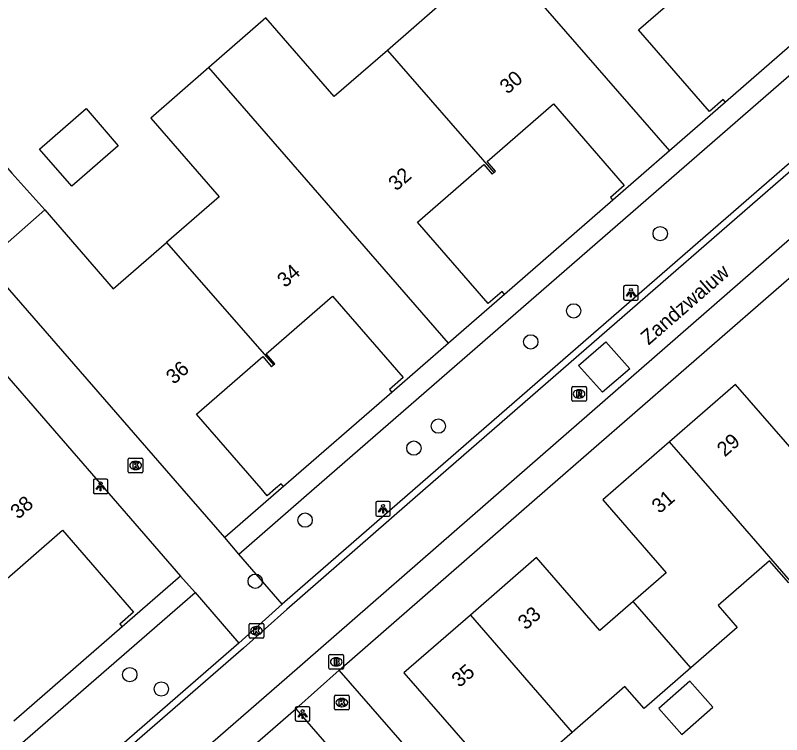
# Model space of a CAD drawing. Extents: x 155888 to 156864, y 383882 to 384671.
# Drawn here: x 156227.5 to 156279.9, y 384233.2 to 384282.3 of the extents above; entities that cross this region are included whole.
import ezdxf

# ---------------------------------------------------------------- set-up
doc = ezdxf.new("R2010")
doc.units = 0
for name, color, linetype in [('IMGEO_Boom', 7, 'Continuous'), ('IMGEO_Brandkraan', 7, 'Continuous'), ('IMGEO_Kolk', 7, 'Continuous'), ('IMGEO_Lichtpunt', 7, 'Continuous'), ('IMGEO_Openbare_ruimte_label', 7, 'Continuous'), ('IMGEO_Pand', 7, 'Continuous'), ('IMGEO_Pand_nummerreeks', 7, 'Continuous'), ('IMGEO_Rijbaan_lokaal_gesloten', 7, 'Continuous'), ('IMGEO_Rijbaan_lokaal_open', 7, 'Continuous'), ('IMGEO_Rioolput', 7, 'Continuous'), ('IMGEO_Voetpad_open', 7, 'Continuous')]:
    doc.layers.add(name, color=color, linetype=linetype)

msp = doc.modelspace()

# ---------------------------------------------------------------- linework, layer by layer
at = {"layer": 'IMGEO_Boom'}
for centre in [(156271.565, 384267.4), (156265.659, 384262.13), (156262.726, 384260.015), (156256.417, 384254.264), (156254.745, 384252.761), (156247.318, 384247.848), (156243.914, 384243.68), (156235.344, 384237.306), (156237.497, 384236.332)]:
    msp.add_circle(centre, 0.489, dxfattribs=at)
at = {"layer": 'IMGEO_Brandkraan'}
for p, q in [((156248.947, 384237.751), (156248.947, 384238.603)), ((156249.022, 384238.677), (156249.874, 384238.677)), ((156249.435, 384238.457), (156249.46, 384238.457)), ((156249.948, 384238.603), (156249.948, 384237.751)), ((156249.874, 384237.677), (156249.022, 384237.677)), ((156249.458, 384237.897), (156249.433, 384237.897))]:
    msp.add_line(p, q, dxfattribs=at)
for points in [[(156248.947, 384237.751), (156248.947, 384238.603)], [(156249.022, 384238.677), (156249.874, 384238.677)], [(156249.295, 384238.377), (156249.295, 384237.977), (156249.508, 384237.977)], [(156249.526, 384238.377), (156249.295, 384238.377)], [(156249.474, 384238.296), (156249.42, 384238.296), (156249.42, 384238.22)], [(156249.42, 384238.22), (156249.473, 384238.22)], [(156249.948, 384238.603), (156249.948, 384237.751)], [(156249.874, 384237.677), (156249.022, 384237.677)], [(156249.482, 384238.144), (156249.42, 384238.144), (156249.42, 384238.063)], [(156249.42, 384238.063), (156249.482, 384238.063)]]:
    msp.add_lwpolyline(points, dxfattribs=at)
for centre, radius, start, end in [((156249.024, 384238.601), 0.0765, 91.552, 178.448), ((156249.024, 384238.601), 0.0765, 91.552, 178.448), ((156249.475, 384238.258), 0.0379, 267.8285, 90.9355), ((156249.53, 384238.232), 0.145, 59.4692, 91.5367), ((156249.555, 384238.279), 0.0922, 285.5137, 58.1501), ((156249.56, 384238.087), 0.105, 301.3115, 78.989), ((156249.872, 384238.601), 0.0765, 1.552, 88.448), ((156249.872, 384238.601), 0.0765, 1.552, 88.448), ((156249.024, 384237.753), 0.0765, 181.552, 268.448), ((156249.024, 384237.753), 0.0765, 181.552, 268.448), ((156249.483, 384238.103), 0.0404, 269.8759, 90.5077), ((156249.514, 384238.228), 0.251, 268.6676, 293.5347), ((156249.872, 384237.753), 0.0765, 271.552, 358.448), ((156249.872, 384237.753), 0.0765, 271.552, 358.448)]:
    msp.add_arc(centre, radius, start, end, dxfattribs=at)
for centre, major_axis, ratio, start_param, end_param in [((156249.434, 384238.177), (-0.387, 0.002), 0.722429, 4.712389, 7.853982), ((156249.459, 384238.177), (-0.39, 0.002), 0.717154, 1.570796, 4.712389)]:
    msp.add_ellipse(centre, major_axis=major_axis, ratio=ratio, start_param=start_param, end_param=end_param, dxfattribs=at)
at = {"layer": 'IMGEO_Kolk'}
for p, q in [((156235.246, 384251.155), (156235.246, 384252.007)), ((156235.321, 384252.081), (156236.173, 384252.081)), ((156235.734, 384251.861), (156235.759, 384251.861)), ((156236.247, 384252.007), (156236.247, 384251.155)), ((156235.757, 384251.301), (156235.732, 384251.301)), ((156236.173, 384251.081), (156235.321, 384251.081)), ((156243.565, 384240.802), (156244.417, 384240.802)), ((156243.49, 384239.876), (156243.49, 384240.728)), ((156243.978, 384240.582), (156244.003, 384240.582)), ((156244.491, 384240.728), (156244.491, 384239.876)), ((156244.417, 384239.802), (156243.565, 384239.802)), ((156244.001, 384240.022), (156243.976, 384240.022)), ((156249.325, 384234.974), (156249.325, 384235.826)), ((156249.4, 384235.9), (156250.252, 384235.9)), ((156249.813, 384235.68), (156249.838, 384235.68)), ((156250.326, 384235.826), (156250.326, 384234.974)), ((156249.836, 384235.12), (156249.811, 384235.12)), ((156250.252, 384234.9), (156249.4, 384234.9))]:
    msp.add_line(p, q, dxfattribs=at)
for points in [[(156235.246, 384251.155), (156235.246, 384252.007)], [(156235.321, 384252.081), (156236.173, 384252.081)], [(156235.567, 384251.781), (156235.69, 384251.781), (156235.69, 384251.63), (156235.82, 384251.781), (156235.984, 384251.781), (156235.838, 384251.63), (156235.991, 384251.381), (156235.839, 384251.381), (156235.754, 384251.545), (156235.69, 384251.478), (156235.69, 384251.381), (156235.567, 384251.381), (156235.567, 384251.781)], [(156236.247, 384252.007), (156236.247, 384251.155)], [(156236.173, 384251.081), (156235.321, 384251.081)], [(156243.565, 384240.802), (156244.417, 384240.802)], [(156243.49, 384239.876), (156243.49, 384240.728)], [(156243.811, 384240.502), (156243.934, 384240.502), (156243.934, 384240.351), (156244.064, 384240.502), (156244.228, 384240.502), (156244.082, 384240.351), (156244.235, 384240.102), (156244.083, 384240.102), (156243.998, 384240.266), (156243.934, 384240.199), (156243.934, 384240.102), (156243.811, 384240.102), (156243.811, 384240.502)], [(156244.491, 384240.728), (156244.491, 384239.876)], [(156244.417, 384239.802), (156243.565, 384239.802)], [(156249.325, 384234.974), (156249.325, 384235.826)], [(156249.4, 384235.9), (156250.252, 384235.9)], [(156249.646, 384235.6), (156249.769, 384235.6), (156249.769, 384235.449), (156249.899, 384235.6), (156250.063, 384235.6), (156249.917, 384235.449), (156250.07, 384235.2), (156249.918, 384235.2), (156249.833, 384235.364), (156249.769, 384235.297), (156249.769, 384235.2), (156249.646, 384235.2), (156249.646, 384235.6)], [(156250.326, 384235.826), (156250.326, 384234.974)], [(156250.252, 384234.9), (156249.4, 384234.9)]]:
    msp.add_lwpolyline(points, dxfattribs=at)
for centre, start, end in [((156235.323, 384252.005), 91.552, 178.448), ((156235.323, 384252.005), 91.552, 178.448), ((156236.171, 384252.005), 1.552, 88.448), ((156236.171, 384252.005), 1.552, 88.448), ((156235.323, 384251.157), 181.552, 268.448), ((156235.323, 384251.157), 181.552, 268.448), ((156236.171, 384251.157), 271.552, 358.448), ((156236.171, 384251.157), 271.552, 358.448), ((156243.567, 384240.726), 91.552, 178.448), ((156243.567, 384240.726), 91.552, 178.448), ((156244.415, 384240.726), 1.552, 88.448), ((156244.415, 384240.726), 1.552, 88.448), ((156243.567, 384239.878), 181.552, 268.448), ((156243.567, 384239.878), 181.552, 268.448), ((156244.415, 384239.878), 271.552, 358.448), ((156244.415, 384239.878), 271.552, 358.448), ((156249.402, 384235.824), 91.552, 178.448), ((156249.402, 384235.824), 91.552, 178.448), ((156250.25, 384235.824), 1.552, 88.448), ((156250.25, 384235.824), 1.552, 88.448), ((156249.402, 384234.976), 181.552, 268.448), ((156249.402, 384234.976), 181.552, 268.448), ((156250.25, 384234.976), 271.552, 358.448), ((156250.25, 384234.976), 271.552, 358.448)]:
    msp.add_arc(centre, 0.0765, start, end, dxfattribs=at)
for centre, major_axis, ratio, start_param, end_param in [((156235.733, 384251.581), (-0.387, 0.002), 0.722429, 4.712389, 7.853982), ((156235.758, 384251.581), (-0.39, 0.002), 0.717154, 1.570796, 4.712389), ((156243.977, 384240.302), (-0.387, 0.002), 0.722429, 4.712389, 7.853982), ((156244.002, 384240.302), (-0.39, 0.002), 0.717154, 1.570796, 4.712389), ((156249.812, 384235.4), (-0.387, 0.002), 0.722429, 4.712389, 7.853982), ((156249.837, 384235.4), (-0.39, 0.002), 0.717154, 1.570796, 4.712389)]:
    msp.add_ellipse(centre, major_axis=major_axis, ratio=ratio, start_param=start_param, end_param=end_param, dxfattribs=at)
at = {"layer": 'IMGEO_Lichtpunt'}
for p, q in [((156269.971, 384263.859), (156269.163, 384263.859)), ((156269.971, 384263.859), (156269.163, 384263.859)), ((156269.069, 384263.764), (156269.069, 384262.957)), ((156269.069, 384263.764), (156269.069, 384262.957)), ((156270.065, 384262.957), (156270.065, 384263.764)), ((156270.065, 384262.957), (156270.065, 384263.764)), ((156269.163, 384262.863), (156269.971, 384262.863)), ((156269.163, 384262.863), (156269.971, 384262.863)), ((156232.858, 384250.557), (156232.858, 384249.75)), ((156232.858, 384250.557), (156232.858, 384249.75)), ((156233.76, 384250.652), (156232.952, 384250.652)), ((156233.76, 384250.652), (156232.952, 384250.652)), ((156233.854, 384249.75), (156233.854, 384250.557)), ((156233.854, 384249.75), (156233.854, 384250.557)), ((156232.952, 384249.656), (156233.76, 384249.656)), ((156232.952, 384249.656), (156233.76, 384249.656)), ((156252.14, 384249.021), (156252.14, 384248.214)), ((156252.14, 384249.021), (156252.14, 384248.214)), ((156253.042, 384249.116), (156252.234, 384249.116)), ((156253.042, 384249.116), (156252.234, 384249.116)), ((156253.136, 384248.214), (156253.136, 384249.021)), ((156253.136, 384248.214), (156253.136, 384249.021)), ((156252.234, 384248.12), (156253.042, 384248.12)), ((156252.234, 384248.12), (156253.042, 384248.12)), ((156247.552, 384235.119), (156246.744, 384235.119)), ((156247.552, 384235.119), (156246.744, 384235.119)), ((156246.65, 384235.024), (156246.65, 384234.217)), ((156246.65, 384235.024), (156246.65, 384234.217)), ((156247.646, 384234.217), (156247.646, 384235.024)), ((156247.646, 384234.217), (156247.646, 384235.024)), ((156246.744, 384234.123), (156247.552, 384234.123)), ((156246.744, 384234.123), (156247.552, 384234.123))]:
    msp.add_line(p, q, dxfattribs=at)
for points in [[(156269.443, 384263.428), (156269.482, 384263.4), (156269.294, 384263.138), (156269.256, 384263.165), (156269.443, 384263.428)], [(156269.545, 384263.38), (156269.592, 384263.38), (156269.592, 384263.058), (156269.545, 384263.058), (156269.545, 384263.38)], [(156269.655, 384263.4), (156269.693, 384263.427), (156269.88, 384263.165), (156269.841, 384263.137), (156269.655, 384263.4)], [(156233.232, 384250.221), (156233.271, 384250.193), (156233.083, 384249.931), (156233.045, 384249.958), (156233.232, 384250.221)], [(156233.444, 384250.193), (156233.482, 384250.22), (156233.669, 384249.958), (156233.63, 384249.93), (156233.444, 384250.193)], [(156233.334, 384250.173), (156233.381, 384250.173), (156233.381, 384249.851), (156233.334, 384249.851), (156233.334, 384250.173)], [(156252.514, 384248.685), (156252.553, 384248.657), (156252.365, 384248.395), (156252.327, 384248.422), (156252.514, 384248.685)], [(156252.616, 384248.637), (156252.663, 384248.637), (156252.663, 384248.315), (156252.616, 384248.315), (156252.616, 384248.637)], [(156252.726, 384248.657), (156252.764, 384248.684), (156252.951, 384248.422), (156252.912, 384248.394), (156252.726, 384248.657)], [(156247.024, 384234.688), (156247.063, 384234.66), (156246.875, 384234.398), (156246.837, 384234.425), (156247.024, 384234.688)], [(156247.126, 384234.64), (156247.173, 384234.64), (156247.173, 384234.318), (156247.126, 384234.318), (156247.126, 384234.64)], [(156247.236, 384234.66), (156247.274, 384234.687), (156247.461, 384234.425), (156247.422, 384234.397), (156247.236, 384234.66)]]:
    msp.add_lwpolyline(points, dxfattribs=at)
for centre in [(156269.568, 384263.562), (156233.357, 384250.355), (156252.639, 384248.819), (156247.149, 384234.822)]:
    msp.add_circle(centre, 0.0994, dxfattribs=at)
for centre, start, end in [((156269.163, 384263.764), 90, 180), ((156269.163, 384263.764), 90, 180), ((156269.971, 384263.764), 0, 90), ((156269.971, 384263.764), 0, 90), ((156269.163, 384262.957), 180, 270), ((156269.163, 384262.957), 180, 270), ((156269.971, 384262.957), 270, 0), ((156269.971, 384262.957), 270, 360), ((156232.952, 384250.557), 90, 180), ((156232.952, 384250.557), 90, 180), ((156233.76, 384250.557), 0, 90), ((156233.76, 384250.557), 0, 90), ((156232.952, 384249.75), 180, 270), ((156232.952, 384249.75), 180, 270), ((156233.76, 384249.75), 270, 0), ((156233.76, 384249.75), 270, 360), ((156252.234, 384249.021), 90, 180), ((156252.234, 384249.021), 90, 180), ((156253.042, 384249.021), 0, 90), ((156253.042, 384249.021), 0, 90), ((156252.234, 384248.214), 180, 270), ((156252.234, 384248.214), 180, 270), ((156253.042, 384248.214), 270, 0), ((156253.042, 384248.214), 270, 360), ((156246.744, 384235.024), 90, 180), ((156246.744, 384235.024), 90, 180), ((156247.552, 384235.024), 0, 90), ((156247.552, 384235.024), 0, 90), ((156246.744, 384234.217), 180, 270), ((156246.744, 384234.217), 180, 270), ((156247.552, 384234.217), 270, 0), ((156247.552, 384234.217), 270, 360)]:
    msp.add_arc(centre, 0.0946, start, end, dxfattribs=at)
at = {"layer": 'IMGEO_Pand'}
for points in [[(156255.842, 384291.844), (156272.197, 384273.042)], [(156254.725, 384290.873), (156251.887, 384288.407), (156256.551, 384283.041), (156252.943, 384279.906)], [(156276.031, 384276.373), (156275.868, 384276.562), (156274.923, 384275.741), (156270.089, 384281.305), (156274.619, 384285.241), (156275.19, 384284.585), (156275.317, 384284.696)], [(156252.943, 384279.906), (156249.312, 384276.751), (156244.648, 384282.117), (156240.753, 384278.732)], [(156252.943, 384279.906), (156260.214, 384271.572)], [(156240.753, 384278.732), (156236.782, 384275.282), (156241.446, 384269.916), (156237.846, 384266.788)], [(156257.1, 384259.924), (156240.753, 384278.732)], [(156276.031, 384276.373), (156272.197, 384273.042)], [(156234.558, 384273.401), (156231.391, 384270.643), (156229.191, 384273.169), (156232.36, 384275.929), (156234.558, 384273.401)], [(156260.214, 384271.572), (156260.319, 384271.664), (156259.748, 384272.32), (156264.277, 384276.255), (156269.111, 384270.691), (156268.169, 384269.873), (156268.332, 384269.684)], [(156272.197, 384273.042), (156268.332, 384269.684)], [(156222.851, 384268.495), (156226.866, 384272.016), (156227.303, 384271.525), (156229.535, 384269.017)], [(156260.934, 384263.255), (156260.771, 384263.444), (156259.826, 384262.623), (156254.992, 384268.187), (156259.522, 384272.123), (156260.093, 384271.467), (156260.214, 384271.572)], [(156229.535, 384269.017), (156225.482, 384265.463)], [(156229.535, 384269.017), (156234.215, 384263.633), (156237.846, 384266.788)], [(156237.846, 384266.788), (156245.167, 384258.447)], [(156241.836, 384246.66), (156238.931, 384250), (156225.482, 384265.463)], [(156222.476, 384262.828), (156233.627, 384250), (156238.811, 384244.035)], [(156245.167, 384258.447), (156245.249, 384258.518), (156244.652, 384259.202), (156249.18, 384263.137), (156254.014, 384257.573), (156253.072, 384256.755), (156253.235, 384256.566)], [(156260.934, 384263.255), (156257.1, 384259.924)], [(156257.1, 384259.924), (156253.235, 384256.566)], [(156245.845, 384250.143), (156245.682, 384250.332), (156245.3, 384250), (156244.737, 384249.511), (156244.313, 384250), (156239.903, 384255.075), (156244.425, 384259.005), (156245.02, 384258.319), (156245.167, 384258.447)], [(156283.323, 384254.106), (156281.046, 384252.126), (156276.719, 384257.109), (156272.206, 384253.19)], [(156272.206, 384253.19), (156268.532, 384250), (156267.642, 384249.227), (156271.969, 384244.244), (156269.721, 384242.29)], [(156280.466, 384243.678), (156274.976, 384250), (156272.206, 384253.19)], [(156245.845, 384250.143), (156245.68, 384250), (156241.836, 384246.66)], [(156226.713, 384242.443), (156226.823, 384242.539), (156226.226, 384243.223), (156230.755, 384247.157), (156235.602, 384241.577), (156234.659, 384240.759), (156234.822, 384240.57)], [(156269.721, 384242.29), (156267.446, 384240.312), (156263.119, 384245.295), (156258.604, 384241.375)], [(156280.466, 384243.678), (156280.342, 384243.57), (156279.031, 384245.079), (156275.514, 384242.025), (156276.824, 384240.515), (156273.658, 384237.765)], [(156238.811, 384244.035), (156234.822, 384240.57)], [(156273.658, 384237.765), (156269.721, 384242.29)], [(156258.604, 384241.375), (156254.07, 384237.439), (156258.397, 384232.456), (156255.981, 384230.358)], [(156258.604, 384241.375), (156265.545, 384233.366)], [(156273.658, 384237.765), (156270.464, 384234.991), (156269.153, 384236.5), (156265.545, 384233.366)], [(156275.162, 384235.082), (156273.601, 384236.855), (156271.478, 384234.986), (156273.039, 384233.213), (156275.162, 384235.082)], [(156265.545, 384233.366), (156261.925, 384230.222), (156263.236, 384228.712), (156259.915, 384225.828)]]:
    msp.add_lwpolyline(points, dxfattribs=at)
at = {"layer": 'IMGEO_Rijbaan_lokaal_gesloten'}
for points in [[(156291.303, 384281.083), (156255.539, 384250), (156246.06, 384241.762), (156243.102, 384239.116), (156204.848, 384205.921), (156197.157, 384199.948), (156195.594, 384198.757), (156195.167, 384198.429)], [(156289.497, 384274.681), (156289.299, 384274.644), (156289.1, 384274.566), (156260.888, 384250), (156246.061, 384237.089), (156208.721, 384204.654)]]:
    msp.add_lwpolyline(points, dxfattribs=at)
at = {"layer": 'IMGEO_Rijbaan_lokaal_open'}
for points in [[(156291.002, 384281.43), (156254.838, 384250), (156245.758, 384242.109)], [(156265.982, 384258.403), (156267.853, 384260.018), (156269.485, 384258.172), (156267.635, 384256.588), (156265.982, 384258.403)], [(156242.787, 384245.529), (156241.836, 384246.66)], [(156245.758, 384242.109), (156242.787, 384245.529)], [(156239.812, 384242.902), (156238.811, 384244.035)], [(156239.812, 384242.902), (156242.8, 384239.463)], [(156242.8, 384239.463), (156245.758, 384242.109)], [(156242.8, 384239.463), (156204.556, 384206.277), (156196.854, 384200.295)]]:
    msp.add_lwpolyline(points, dxfattribs=at)
at = {"layer": 'IMGEO_Rioolput'}
for p, q in [((156265.523, 384256.036), (156265.523, 384256.888)), ((156265.598, 384256.962), (156266.45, 384256.962)), ((156266.011, 384256.742), (156266.036, 384256.742)), ((156266.524, 384256.888), (156266.524, 384256.036)), ((156266.034, 384256.182), (156266.009, 384256.182)), ((156266.45, 384255.962), (156265.598, 384255.962))]:
    msp.add_line(p, q, dxfattribs=at)
for points in [[(156265.523, 384256.036), (156265.523, 384256.888)], [(156265.598, 384256.962), (156266.45, 384256.962)], [(156266.112, 384256.66), (156265.86, 384256.662), (156265.86, 384256.262)], [(156266.038, 384256.581), (156265.984, 384256.581), (156265.984, 384256.5)], [(156265.984, 384256.5), (156266.036, 384256.5)], [(156266.524, 384256.888), (156266.524, 384256.036)], [(156265.86, 384256.262), (156265.984, 384256.262), (156265.984, 384256.424), (156265.995, 384256.424)], [(156266.042, 384256.395), (156266.113, 384256.262), (156266.253, 384256.262), (156266.188, 384256.388)], [(156266.45, 384255.962), (156265.598, 384255.962)]]:
    msp.add_lwpolyline(points, dxfattribs=at)
for centre, radius, start, end in [((156265.6, 384256.886), 0.0765, 91.552, 178.448), ((156265.6, 384256.886), 0.0765, 91.552, 178.448), ((156266.02, 384256.689), 0.19, 274.7715, 282.9687), ((156266.044, 384256.485), 0.0964, 77.0061, 93.1865), ((156266.058, 384256.542), 0.0378, 276.6634, 79.6772), ((156266.111, 384256.55), 0.109, 350.3612, 89.416), ((156266.109, 384256.55), 0.112, 277.5842, 350.9817), ((156266.448, 384256.886), 0.0765, 1.552, 88.448), ((156266.448, 384256.886), 0.0765, 1.552, 88.448), ((156265.6, 384256.038), 0.0765, 181.552, 268.448), ((156265.6, 384256.038), 0.0765, 181.552, 268.448), ((156265.994, 384256.371), 0.0533, 26.0293, 88.6989), ((156266.093, 384256.335), 0.108, 29.5134, 73.7905), ((156266.448, 384256.038), 0.0765, 271.552, 358.448), ((156266.448, 384256.038), 0.0765, 271.552, 358.448)]:
    msp.add_arc(centre, radius, start, end, dxfattribs=at)
for centre, major_axis, ratio, start_param, end_param in [((156266.01, 384256.462), (-0.387, 0.002), 0.722429, 4.712389, 7.853982), ((156266.035, 384256.462), (-0.39, 0.002), 0.717154, 1.570796, 4.712389)]:
    msp.add_ellipse(centre, major_axis=major_axis, ratio=ratio, start_param=start_param, end_param=end_param, dxfattribs=at)
at = {"layer": 'IMGEO_Voetpad_open'}
for points in [[(156242.787, 384245.529), (156247.93, 384250), (156288.362, 384285.147)], [(156283.4, 384282.776), (156276.031, 384276.373)], [(156249.638, 384237.607), (156263.88, 384250), (156290.715, 384273.351)], [(156268.332, 384269.684), (156260.934, 384263.255)], [(156253.235, 384256.566), (156245.845, 384250.143)], [(156196.854, 384200.295), (156194.203, 384203.337), (156239.812, 384242.902)], [(156234.822, 384240.57), (156227.423, 384234.143)], [(156246.679, 384234.978), (156249.638, 384237.607)], [(156255.981, 384230.358), (156249.638, 384237.607)], [(156242.149, 384231.047), (156246.679, 384234.978)], [(156246.679, 384234.978), (156268.595, 384209.753)]]:
    msp.add_lwpolyline(points, dxfattribs=at)

# ---------------------------------------------------------------- texts
at = {"layer": 'IMGEO_Openbare_ruimte_label'}
msp.add_text('Zandzwaluw', height=1, rotation=41.0241, dxfattribs=at).set_placement((156270.77, 384259.753))
at = {"layer": 'IMGEO_Pand_nummerreeks'}
for s, rotation, p in [('30', 40.9894, (156261.143, 384276.871)), ('32', 40.9888, (156253.544, 384270.267)), ('34', 40.9888, (156245.951, 384263.67)), ('36', 40.9888, (156238.356, 384257.07)), ('29', 40.9694, (156275.976, 384252.121)), ('31', 40.9694, (156271.523, 384248.254)), ('38', 40.9779, (156227.726, 384247.865)), ('33', 40.9633, (156262.383, 384240.313)), ('35', 40.9633, (156257.858, 384236.385))]:
    msp.add_text(s, height=1, rotation=rotation, dxfattribs=at).set_placement(p)

doc.saveas('drawing.dxf')
